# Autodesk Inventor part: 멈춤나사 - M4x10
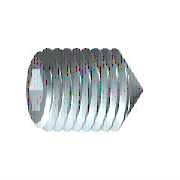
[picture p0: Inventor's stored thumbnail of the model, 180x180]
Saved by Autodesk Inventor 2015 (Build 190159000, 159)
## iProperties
Created: 2012-02
Part Number: 멈춤나사 - M4x10
Material: 강철, 연강
Description: 6각 소켓 머리 없는 멈춤 나사
Document SubType Name: Modeling
Standard: KS B 1028
Designer: mduedu
Standards Organization: KS
Language: ko-KR
Size Designation: 원추점 M4x10
Categories: <MemberInstance><Categories><Category DisplayName="조임쇠" InternalName="e4da775c-781d-43d5-af7c-5136215cf5a6" Mnemonic="FSTN"><Category DisplayName="볼트" InternalN
Density: 1 g/cm^3
Appearance: 강철
Author: mduedu
IsCustomPart: 1
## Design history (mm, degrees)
sketch "스케치1"
  geometry: L1 (0, 0)-(6.833, 0); L2 (10, 1.155)-(10, 2); L3 (10, 2)-(0, 2); L4 (10, 1.155)-(7.5, 1.155); L5 (7.5, 1.155)-(6.833, 0); L6 (0, -0.4)-(0, 2.4) reference; L7 (0, 2)-(0, 0)
  constraints: 13 end point, 3 parallel, 1 collinear, 1 perpendicular, 1 point on line
  dimensions: "d0" = 2.5 distance of L2.start L4.end (= INTI); "d1" = 60 deg angle of L5 L1; "d2" = 4 diameter of L3 L1 (= NND); "d3" = 2.3094 diameter of L4 L1 (= 1.1547 x SW); "d5" = 10 distance from line of L2 L3.end (= NLG)
revolve "본체" sketch "스케치1" stored, may be unused: angle "d6" = 90 deg
sketch "스케치2"
  geometry: L1 (-0.577, 1)-(0.577, 1); L2 (0.577, 1)-(1.155, 0); L3 (1.155, 0)-(0.577, -1); L4 (0.577, -1)-(-0.577, -1); L5 (-0.577, -1)-(-1.155, 0); L6 (-1.155, 0)-(-0.577, 1); 3 further points
  constraints: 12 end point, 1 coincident, 1 horizontal, 13 other
extrude "슬롯" join sketch "스케치2" taper "d7" = 0 deg; stored distance "d21" = 10
workaxis "Work Axis1"
workplane "Work Plane1"
body "Solid1"
feature "스레드" dims "d12" = 10 (= NLG), "d13" = 0
chamfer "모따기1" distance "d8" = 1.8 (computed from NND, SPD, FAWI); stored, may be unused: angle "d9" = 45 deg (= FAWI), second distance "d34" = 1.8 (computed from NND, SPD, FAWI)
chamfer "모따기2" distance "d10" = 0.42941 (= -0.5 x GD1 + 0.5 x NND); stored, may be unused: angle "d11" = 45 deg (= FAWI), second distance "d35" = 0.42941 (= -0.5 x GD1 + 0.5 x NND)
other parameters: "NND" = 4 [user parameter; used in 5 equation terms], "NLG" = 10 [user parameter; used in 2 equation terms], "INTI" = 2.5 [user parameter; used in 1 equation term], "FAWI" = 45 deg [user parameter; used in 4 equation terms], "SW" = 2 [user parameter; used in 2 equation terms], "GD1" = 3.14117 (= THREADDIA - 1.2269 x PTC) [user parameter; used in 2 equation terms], "d4" = 0, "FAWI1" = 45 deg [user parameter], "SPD" = 0.4 [user parameter; used in 2 equation terms], "d36" = 0, "d37" = 0, "GUL" = 0.42941 (= 0.61345 x PTC) [user parameter], "TPU" = 14.28571 (computed from PTC) [user parameter], "TOA" = 30 deg [user parameter], "THREADDIA" = 4 [user parameter; used in 1 equation term], "PTC" = 0.7 [user parameter; used in 4 equation terms], "GAL" = 0.42941 (= 0.61345 x PTC) [user parameter], "E0" = 2.31 (= 1.155 x SW) [user parameter]
